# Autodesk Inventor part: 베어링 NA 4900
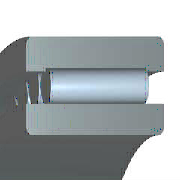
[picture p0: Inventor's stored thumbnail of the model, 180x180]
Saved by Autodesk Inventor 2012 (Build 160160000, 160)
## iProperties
Created: 2014-07
Part Number: 베어링 NA 4900
Material: Steel, Mild
Description: 니들 롤러 베어링 - 경계 치수 및 공차
Document SubType Name: Modeling
Standard: KS B 2029
Designer: KYOUNG IL JANG
Standards Organization: KS
Language: ko-KR
Size Designation: NA 4900 - 10 x 22 x 13
Categories: <MemberInstance><Categories><Category DisplayName="샤프트 부품" InternalName="7f7aeb1f-a693-4053-b835-cee3144e0d98" Mnemonic="SHFT"><Category DisplayName="베어링" Inter
Density: 7.86 g/cm^3
Mass: 23.8214 g
Surface Area: 38.613 cm^2
Volume: 3.03071 cm^3
Company: 한국ATC센터
IsCustomPart: 0
Author: KYOUNG IL JANG
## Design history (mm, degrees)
revolve "본체" stored, may be unused: angle "d17" = 90 deg
revolve "롤러" stored, may be unused: angle "d18" = 90 deg
pattern_circular "IDS_ARRAYROLLER[SIMPL:T]" dims angle "d2" = 360 deg
body "Solid1"
sketch "스케치"
  geometry: L1 (1.857, 9)-(11.143, 9); L2 (11.143, 9)-(11.143, 7); L3 (13, 7)-(0, 7); L4 (1.857, 7)-(1.857, 9); L5 (1.857, 8)-(11.143, 8); L6 (6.5, 8)-(6.5, 7); L7 (0, 5)-(13, 5); L8 (0, 11)-(13, 11); L9 (13, 5)-(13, 7); L10 (13, 8.8)-(13, 11); L11 (1.857, 8.8)-(0, 8.8); L12 (11.143, 8.8)-(13, 8.8); L13 (-6, 0)-(36, 0) reference; L14 (0, -1.9)-(0, 14.9) reference
  constraints: 24 end point, 8 point on line, 3 midpoint, 3 parallel, 3 perpendicular, 2 symmetric about line, 1 horizontal, 1 other
  dimensions: "d6" = 10 diameter of L7 L13 (= WD); "d7" = 14 diameter of L3 L13 (= KID1); "d8" = 22 diameter of L8 L13 (= BD); "d9" = 16 diameter of L6.start L13 (= 0.5 x WD + 0.5 x BD); "d10" = 17.6 diameter of L12 L13 (= 0.9 x BD + 0.9 x WD - 0.8 x KID1); "d11" = 18 diameter of L1 L13 (= BD + WD - KID1); "d12" = 1.85714 distance between parallel lines of L14 L4 (= 0.142857 x KB); "d13" = 13 distance between parallel lines of L14 L9 (= KB); "d14" = 11.14286 distance between parallel lines of L14 L2 (= 0.857143 x KB)
fillet "모깎기1" dims "d0" = 0.3 (= KRS)
other parameters: "WD" = 10 [user parameter; used in 6 equation terms], "BD" = 22 [user parameter; used in 6 equation terms], "KB" = 13 [user parameter; used in 3 equation terms], "KID1" = 14 [user parameter; used in 4 equation terms], "KRS" = 0.3 [user parameter; used in 1 equation term], "d3" = 0, "d4" = 0, "d5" = 0, "d15" = 0, "d16" = 0, "BC0" = 9150000 [user parameter], "WR" = 5 (= 0.5 x WD) [user parameter], "BBA" = 0 [user parameter], "BC" = 8150000 [user parameter], "BR" = 11 (= 0.5 x BD) [user parameter]
